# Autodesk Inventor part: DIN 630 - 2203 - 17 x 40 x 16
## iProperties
Created: 2006-02
Part Number: DIN 630 - 2203 - 17 x 40 x 16
Material: Steel, Mild
Description: Self-Aligning Ball Bearing
Document SubType Name: Modeling
Standard: DIN 630
Designer: Andy Moles
Standards Organization: DIN
Language: en-US
Size Designation: 2203 - 17 x 40 x 16
Categories: <MemberInstance><Categories><Category DisplayName="Shaft Parts" InternalName="7f7aeb1f-a693-4053-b835-cee3144e0d98" Mnemonic="SHFT"><Category DisplayName="Beari
Density: 1 g/cm^3
IsCustomPart: 1
Author: Andy Moles
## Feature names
1. Body [Revolution]
2. Fillet1
3. Ball1 [Revolution]
4. Ball2 [Revolution]
5. Balls1 [Circular Pattern]
6. Balls2 [Rectangular Pattern]
